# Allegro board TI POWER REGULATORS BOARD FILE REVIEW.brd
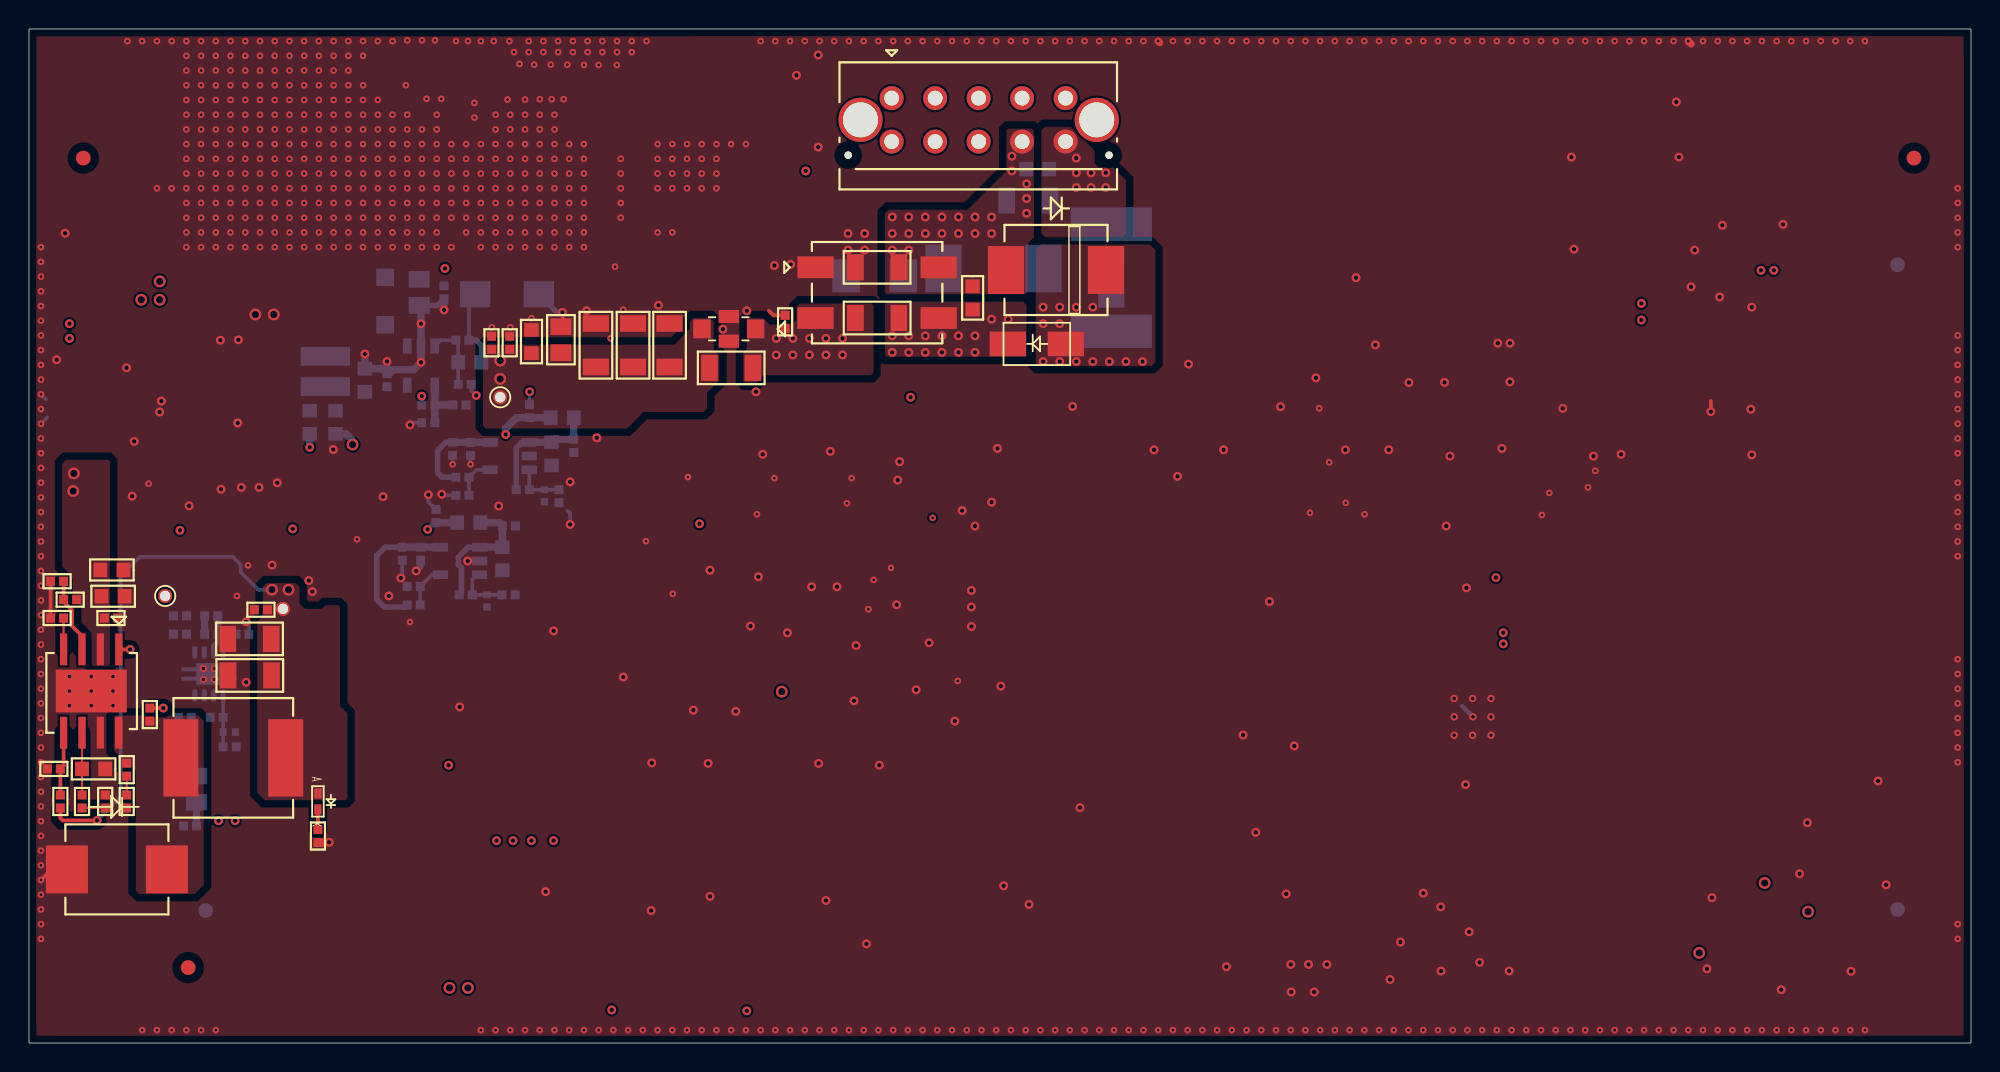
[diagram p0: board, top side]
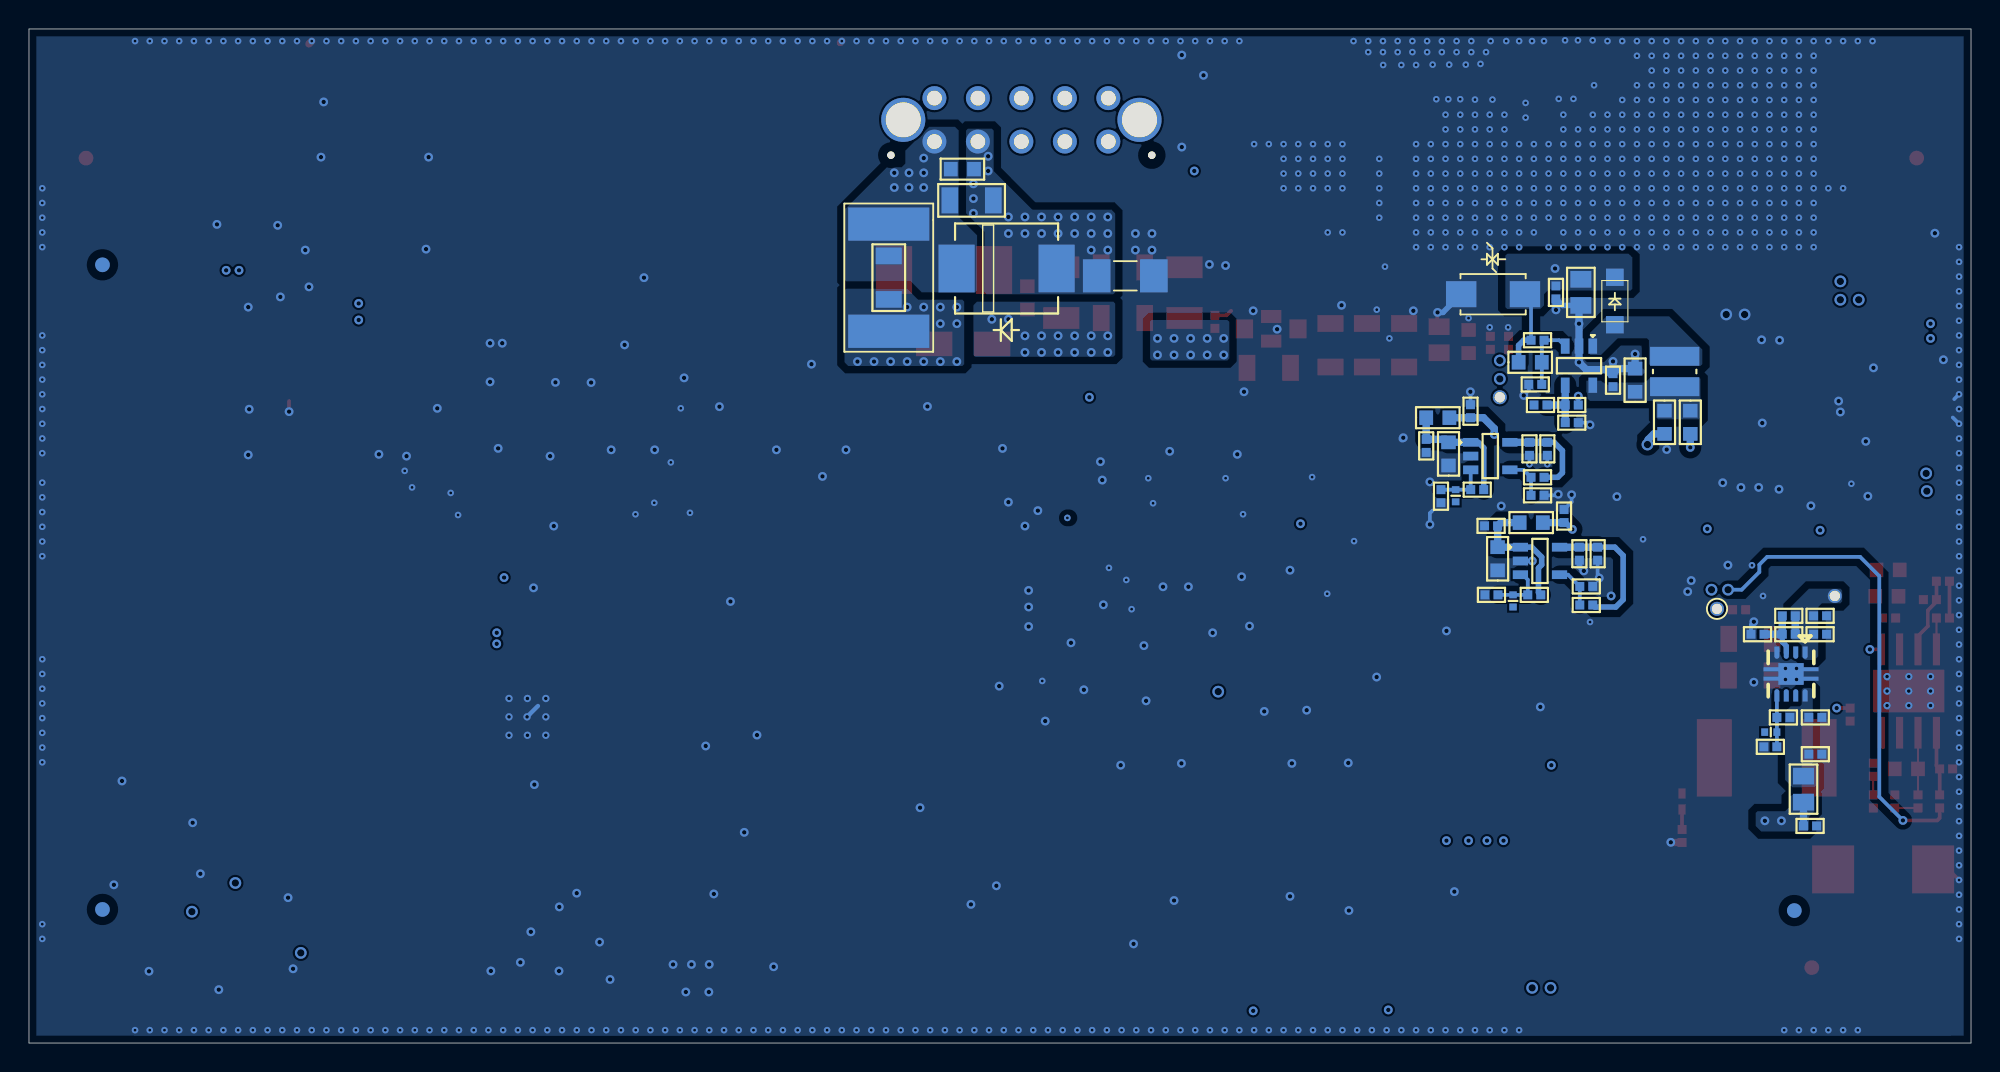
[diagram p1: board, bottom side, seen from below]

Outline 134 x 70 mm; copper layers: TOP, GND, SIG1, SIG2, VCC, BOTTOM. Coordinates in mm from the lower left corner of the outline.
Outline path: 0,70 0,0 134,0 134,70 0,70

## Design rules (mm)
net group DP10: nets CAN1_H CAN1_L
net group DP11: nets CAN2_H CAN2_L
net group POWER: nets LDO1_EN LDO1_FB

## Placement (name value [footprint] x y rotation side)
C106  0.1uF  [0402]  10.41 29.49 180 bottom
C111  2.2uF  [0402]  10.41 28.22 180 bottom
C120  0.1uF  [0402]  12.57 28.22 0 bottom
C484  4.7uF  [0603]  23.18 45.76 90 bottom
C485  100pF  [0603]  30.42 46.99 180 bottom
C486  4.7uF  [0805]  26.92 51.82 270 bottom
C517  0.1uF  [0603]  69.6 60.33 0 bottom
C519  1000pF_3KV  [1808]  60.33 52.96 180 bottom
C523  1uF  [0603]  34.67 48.42 270 top
C524  0.1uF  [0402]  31.91 48.34 270 top
C525  10uF  [0805]  36.7 48.55 270 top
C527  47uF  [1206]  41.68 48.17 270 top
C528  47uF  [1206]  39.12 48.17 270 top
C533  47uF  [1206]  68.96 58.17 0 bottom
C534  0.1uF  [0603]  65.11 51.44 270 top
C540  0.1uF  [0402]  33.17 48.34 270 top
C541  0.1uF  [0402]  52.17 49.78 270 top
C542  47uF  [1206]  44.2 48.17 270 top
C588  4.7uF  [0603]  5.72 32.65 180 top
C590  10000pF  [0402]  5.65 29.34 180 top
C592  22pF  [0603]  4.46 18.92 180 top
C593  10000pF  [0402]  1.94 29.34 0 top
C594  0.1uF  [0402]  8.34 22.67 90 top
C595  47uF  [1206]  15.23 25.38 0 top
C596  47uF  [1206]  15.22 27.9 0 top
C613  4.7uF  [0603]  5.8 30.84 180 top
C614  2200pF  [0402]  3.66 16.68 90 top
C615  0.1uF  [0402]  11.11 14.99 180 bottom
C616  0.1uF  [0402]  10.74 19.94 180 bottom
C620  4.7uF  [0402]  10.74 22.48 180 bottom
C643  0.1uF  [0402]  24.7 45.76 90 bottom
C644  0.1uF  [0402]  28.64 51.82 270 bottom
C648  0.1uF  [0402]  16 29.91 0 top
C670  0.1uF  [0402]  25.76 33.78 270 bottom
C672  0.1uF  [0402]  28.08 36.38 90 bottom
C673  1uF  [0402]  27.02 33.78 270 bottom
C674  0.1uF  [0402]  29.23 41.02 270 bottom
C676  0.1uF  [0402]  34.54 43.61 90 bottom
C677  1uF  [0402]  30.47 41.02 270 bottom
C731  10uF  [0603]  36.05 40.67 90 bottom
C732  10uF  [0603]  32.66 33.43 90 bottom
C733  0.1uF  [0402]  6.74 16.68 90 top
C750  0.1uF  [0402]  33.11 35.7 0 bottom
C751  0.1uF  [0402]  37.59 41.22 270 bottom
D3  LED  [LED_APHXX]  19.94 17.23 270 top
D4  SK53A-LTP  [DIODE_SMA]  71.54 48.26 180 top
D50  MBR0530T1G  [SOD_123]  24.58 49.58 90 bottom
D59  5.0SMDJ18A  [DIODE_DO-214AB]  63.1 53.47 0 bottom
D83  CDBC540-G  [DIODE_SMC-DO-214AB]  2.62 11.99 0 top
D84  5.0SMDJ18A  [DIODE_DO-214AB]  67.41 53.36 0 top
D87  SMAJ18CA  [DIODE_DO-214AC-SMA]  35.18 51.69 180 bottom
E1  ACM9070-701-2PL-TL01  [CMC_ACM9070]  54.27 53.55 0 top
F6  0ZCF0330FF2C  [FUSE_0ZCF0100AF2A]  74.68 56.53 270 bottom
FB33  BLM21SN300SH1D  [0805]  11.56 17.53 90 bottom
FB47  BLM31KN271SN1L  [1206]  74.68 52.83 270 bottom
FB48  BLM31KN271SN1L  [1206]  58.52 50.05 180 top
FB49  BLM31KN271SN1L  [1206]  48.45 46.61 180 top
FB50  BLM31KN271SN1L  [1206]  58.52 53.55 180 top
FB51  74279228111  [0603]  21.15 42.85 270 bottom
FB52  74279228111  [0603]  19.37 42.85 270 bottom
FB67  74279228111  [0603]  30.35 35.93 180 bottom
FB68  74279228111  [0603]  36.79 43.16 180 bottom
J74  0430451024  [MOLEX_430451024]  59.53 65.23 180 top
L4  10uH  [IND_74438336100]  20.45 45.31 90 bottom
L66  4.7uH  [IND_IHLP3232DZERR47M01]  14.1 19.68 0 top
NOREF  -  []  -28.16 28.95 0 top
NOREF#2  -  []  -23.63 27.09 90 top
NOREF#3  -  []  -28.38 27.09 0 top
NOREF#4  -  []  4 0 90 top
NOREF#5  -  []  -33.76 11.11 0 top
NOREF#6  -  []  10.25 37.12 0 top
NOREF#7  -  []  17.75 37.3 0 top
NOREF#8  -  []  -30.16 5.64 0 top
NOREF#9  -  []  0 70 0 top
NOREF#10  -  []  299.21 -187.96 0 top
NOREF#11  -  []  -124.71 2.62 90 top
NOREF#12  -  []  -123.96 2.55 90 top
NOREF#13  -  []  12.25 37.3 0 top
NOREF#14  -  []  -124.71 3.47 0 top
NOREF#15  -  []  -32.31 7.14 90 top
NOREF#16  -  []  -33.76 2.34 90 top
NOREF#17  -  []  -33.16 4.7 0 top
NOREF#18  -  []  -124.88 3.05 0 top
NOREF#19  -  []  10.6 41.2 0 top
NOREF#20  -  []  -30.16 5.64 0 top
NOREF#21  -  []  -30.16 5.64 90 top
NOREF#22  -  []  23.75 37.3 90 top
NOREF#23  -  []  -124.96 3.55 0 top
NOREF#24  -  []  -14.61 3.74 90 top
NOREF#25  -  []  -32.31 7.14 0 top
R19  499E  [0402]  19.94 14.29 270 top
R102  68K, 1%  [0402]  14.73 28.22 0 bottom
R103  33.2K, 1%  [0402]  12.57 29.49 180 bottom
R606  0E  [0402]  29.71 44.04 180 bottom
R607  182K  [0402]  29.91 48.51 0 bottom
R608  13.3K  [0402]  30.07 45.47 180 bottom
R609  51K  [0402]  27.55 44.04 180 bottom
R610  10K  [0402]  27.55 42.82 0 bottom
R706  620K  [0402]  2.84 30.61 0 top
R707  130K  [0402]  1.94 31.88 0 top
R709  10.2k  [0402]  2.17 16.68 270 top
R710  1.96K  [0402]  1.72 18.92 0 top
R711  10K  [0402]  12.95 22.48 180 bottom
R720  37.4K  [0402]  5.26 16.68 270 top
R771  10K  [0402]  33.09 30.94 0 bottom
R772  10K  [0402]  30.13 30.94 0 bottom
R773  10K  [0402]  36.57 37.75 270 bottom
R774  10K  [0402]  34.07 38.2 0 bottom
R839  5.1E  [0402]  6.74 18.87 90 top
R895  0E  [0402C]  31.6 30.52 270 bottom
R896  0E  [0402C]  35.56 37.78 270 bottom
R904  100k  [0402]  26.55 31.52 180 bottom
R905  50k  [0402]  26.55 30.24 0 bottom
R907  187k  [0402]  29.91 39.05 0 bottom
R908  75k  [0402]  29.91 37.81 0 bottom
R921  0E  [0402C]  13.82 21.46 180 bottom
R922  10K  [0402]  13.85 20.45 0 bottom
TP76  TP  [TPXTHX50MIL]  9.4 30.86 0 top
TP79  TP  [TPXTHX50MIL]  32.51 44.58 0 top
TP102  TP  [TPXTHX50MIL]  17.53 29.97 270 bottom
U13  TPS73701DRBR  [PVSONX0_65X3_15X3_15X1_00-9]  11.45 26.95 0 bottom
U25  LM2733XMF/NOPB  [SOT23X0_95X3_05X1_75X1_45-5]  26.1 48.11 0 bottom
U69  YFF31HC2A103MT000N  [EMIFIL_YFF31HC]  50.14 49.3 180 top
U74  TPS54531DDAR  [HSOICX1_27X5_00X4_00X1_70-9]  6.2 27.17 180 top
U77  RT9053AGB  [SOT23X0_95X3_05X1_75X1_10-5]  31.09 34.23 270 bottom
U78  RT9053AGB  [SOT23X0_95X3_05X1_75X1_10-5]  34.52 41.47 270 bottom
UNK*  -  [unnamed#2]  10.99 5.21 0 top
UNK*#2  -  [unnamed#2]  130.07 61.09 0 top
UNK*#3  -  [unnamed#2]  3.75 61.09 0 top
UNK*#4  -  [unnamed#2]  128.93 9.22 180 bottom
UNK*#5  -  [unnamed#2]  128.93 53.72 180 bottom
UNK*#6  -  [unnamed#2]  12.19 9.14 180 bottom

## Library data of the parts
C106 C120 C519 C615 C616 C670 C672 C674 C676 C750 C751 = CAP NP
C111 C484-C486 C620 C643 C644 C673 C677 C731 C732 = CAPACITOR NON-POL
C517 C523-C525 C527 C528 C533 C534 C540-C542 C588 C590 C592-C596 C613 C614 C648 C733 = C
D3 = LED
D4 D59 D84 D87 = DIODE_SCHTKY_4
D50 D83 = DIODE SCHOTTKY
E1 = INDUCTOR IRON_0
F6 = FUSE THERMAL
FB33 FB47-FB52 FB67 FB68 = INDUCTOR FERRITE
J74 = 0430451024_1
L4 L66 = INDUCTOR
R19 R102 R103 R606-R610 R895 R896 R904 R905 R907 R921 = RES
R706 R707 R709-R711 R720 R771-R774 R922 = R_1
R839 R908 = R
TP76 TP79 TP102 = T POINT R
U13 = TPS73701DCQ_1
U25 = LM2733XMF/NOPB
U69 = E_2
U74 = TPS54531DDAR
U77 U78 = TLV70012QDDCRQ1_0

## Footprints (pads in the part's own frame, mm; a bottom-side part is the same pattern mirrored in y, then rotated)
0402
  rect 0.62x0.62 smd: 1(-0.45,0) 2(0.45,0)
0402C
  rect 0.48x0.521 smd: 1(-0.419,0) 2(0.419,0)
0603
  rect 0.95x1 smd: 1(-0.8,0) 2(0.8,0)
0805
  rect 1.15x1.45 smd: 1(-0.9,0) 2(0.9,0)
1206
  rect 1.15x1.8 smd: 1(-1.5,0) 2(1.5,0)
1808
  rect 1.91x2.29 smd: 1(0,0) 2(3.942,0)
CMC_ACM9070
  rect 2.5x1.5 smd: 1(0,0) 2(0,-3.5) 3(8.5,-3.5) 4(8.5,0)
DIODE_DO-214AB
  rect 2.5x3.3 smd: 1(0,0) 2(6.9,0)
DIODE_DO-214AC-SMA
  rect 2.1x1.8 smd: 1(0,0) 2(4.4,0)
DIODE_SMA
  rect 2.5x1.7 smd: 1(0,0) 2(4,0)
DIODE_SMC-DO-214AB
  rect 2.9x3.3 smd: 1(0,0) 2(6.9,0)
EMIFIL_YFF31HC
  rect 1.199x1.301 smd: 1(0,0) 3(3.701,0)
  rect 1.399x0.899 smd: 2(1.849,-0.851) 4(1.849,0.851)
FUSE_0ZCF0100AF2A
  rect 2.301x5.601 smd: 1(0,0) 2(7.399,0)
HSOICX1_27X5_00X4_00X1_70-9
  rect 0.5x2.2 smd: 1(0,0) 2(1.27,0) 3(2.54,0) 4(3.81,0) 5(3.81,5.751) 6(2.54,5.751) 7(1.27,5.751) 8(0,5.751)
  rect 4.9x2.949 smd: 9(1.905,2.875)
IND_74438336100
  rect 1.3x3.4 smd: 1(0,0) 2(2.1,0)
IND_IHLP3232DZERR47M01
  rect 2.413x5.334 smd: 1(-3.619,0) 2(3.619,0)
LED_APHXX
  rect 0.701x0.5 smd: 1(0,0) 2(1.1,0)
MOLEX_430451024
  round 0.51 hole 1.02 unplated: (-15,3.94) (3,3.94)
  round 3.045 hole 2.41: (-14.15,1.5) (2.15,1.5)
  round 1.655 hole 1.02: 1(0,0) 2(-3,0) 3(-6,0) 4(-9,0) 5(-12,0) 6(0,3) 7(-3,3) 8(-6,3) 9(-9,3) 10(-12,3)
PVSONX0_65X3_15X3_15X1_00-9
  custom 0.088x0.088 smd: 1(0,0) 2(0.65,0) 3(1.3,0) 4(1.95,0) 5(1.95,2.95) 6(1.3,2.95) 7(0.65,2.95) 8(0,2.95)
  custom 0.375x0.375 smd: 9(0.975,1.475)
SOD_123
  rect 1.2x1.22 smd: 1(0,0) 2(3.28,0)
SOT23X0_95X3_05X1_75X1_10-5
  rect 0.6x1.05 smd: 1(0,0) 2(0.95,0) 3(1.9,0) 4(1.9,2.7) 5(0,2.7)
SOT23X0_95X3_05X1_75X1_45-5
  rect 0.6x1.05 smd: 1(0,0) 2(0.95,0) 3(1.9,0) 4(1.9,2.7) 5(0,2.7)
TPXTHX50MIL
  round 0.965 hole 0.711: 1(0,0)
unnamed#2
  round 1.016 smd: (0,0)

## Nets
18V_OUT_EN_GPIO1_IO10: R606.1
18V_SHDN: R606.2 R609.1 R610.2 U25.4(S\H\D\N\)
GND: C106.2 C111.2 C484.2 C486.2 C519.2 C523.1 C524.1 C525.1 C527.1 C528.1 C540.1 C541.1 C542.1 C588.1 C590.1 C592.1 C593.1 C595.1 C596.1 C613.1 C615.2 C616.2 C620.2 C643.2 C644.2 C648.1 C670.2 C672.2 C673.2 C674.2 C676.2 C677.2 C731.1 C732.1 C733.1 C750.2 C751.2 D83.1(ANODE) D87.1(A) E1.1 FB50.2 R19.2 R102.2 R608.1 R610.1 R707.1 R710.1 R720.1 R771.2 R773.2 R904.2 R908.1 R922.2 U13.4(GND1) U13.9(PGND) U25.2(GND) U69.2 U69.4 U74.7(GND) U74.9(TP) U77.2(GND) U78.2(GND)
VBAT_12V: C523.2 C524.2 C525.2 C527.2 C528.2 C540.2 C542.2 C588.2 C590.2 C613.2 FB49.2 R706.2 TP79.1(TP) U69.3 U74.2(VIN)
VBAT_12V_EN: R706.1 R707.2 U74.3(EN)
VCC_1V2: C670.1 C673.1 R905.1 U77.5(OUT)
VCC_1V8: C106.1 C111.1 C120.1 R103.2 TP76.1(TP) U13.1(OUT)
VCC_2V8: C674.1 C677.1 R907.1 U78.5(OUT)
VCC_3V3: C615.1 C672.1 C676.1 FB33.1 FB51.2 FB67.2 FB68.2 R609.2
VCC_3V3_LDO: C616.1 C620.1 FB33.2 R711.2 U13.8(IN)
VCC_3V3_LDO2: C732.2 C750.1 FB67.1 R772.1 U77.1(VIN)
VCC_3V3_LDO3: C731.2 C751.1 FB68.1 R774.1 U78.1(VIN)
VCC_5V: C595.2 C596.2 C648.2 D3.1(ANODE) FB52.2 L66.2 R709.2 TP102.1(TP)
VCC_FIL: C484.1 C643.1 FB51.1 FB52.1 L4.1 U25.5(VIN)
VIN_12V: C517.2 C533.2 D59.2(C) F6.1 FB47.1 J74.10(VIN_12)
ANALOG IN_2: J74.5(ANALOG IN_2)
ANALOG_OUT: J74.3(ANALOG OUT)
CAN1_H: J74.7(CAN1_H)
CAN1_L: J74.6(CAN1_L)
CAN2_H: J74.1(CAN2_H)
CAN2_L: J74.2(CAN2_L)
CONN_GND: C517.1 C519.1 C533.1 C534.1 D59.1(A) D84.1(A) E1.4 FB50.1 J74.9(CONN_GND)
LDO1_EN: R711.1 R921.2 R922.1 U13.5(EN)
LDO1_EN_GPIO5_IO00: R921.1
LDO1_FB: C120.2 R102.1 R103.1 U13.3(FB/NR)
LDO2_EN: R771.1 R772.2 R895.1 U77.3(EN)
LDO2_EN_GPIO4_IO10: R895.2
LDO3_EN: R773.1 R774.2 R896.1 U78.3(EN)
LDO3_EN_GPIO4_IO31: R896.2
VOUT_12V: J74.4(VP-P_IN)
VOUT_18V: C485.1 C486.1 C644.1 D50.2(CATHODE) D87.2(C) J74.8(VOUT_18V) R607.2
N16733345: C534.2 D4.2(C) E1.3 FB48.1
N16733349: C541.2 E1.2 FB48.2 FB49.1 U69.1
N16733417: C594.1 D83.2(CATHODE) L66.1 R839.2 U74.8(PH)
N16733425: C733.2 R839.1
N16733771: C592.2 C614.2 U74.6(COMP)
N16733783: C614.1 R720.2
N16733885: C593.2 U74.4(SS)
N16733923: C594.2 U74.1(BOOT)
N16734049: D4.1(A) D84.2(C) F6.2 FB47.2
N16734163: R709.1 R710.2 U74.5(VSENSE)
N16734965: D3.2(CATHODE) R19.1
N16737795: R904.1 R905.2 U77.4(FB)
N16737935: R907.2 R908.2 U78.4(FB)
N16741203: D50.1(ANODE) L4.2 U25.1(SW)
N16741257: C485.2 R607.1 R608.2 U25.3(FB)

Pads without a net: U13 2 6 7

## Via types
v1: diameter 0.61, hole 0.305, TOP to BOTTOM, 257 vias
v2: diameter 0.813, hole 0.508, TOP to BOTTOM, 18 vias
v3: diameter 0.457, hole 0.203, TOP to BOTTOM, 701 vias
v4: diameter 0.508, hole 0.254, TOP to BOTTOM, 22 vias

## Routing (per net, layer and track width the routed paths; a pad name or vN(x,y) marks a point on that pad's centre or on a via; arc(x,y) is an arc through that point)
18V_SHDN: length 3.8
  BOTTOM w0.508: R606.2 R609.1 ; R609.1 U25.4 ; R609.1 R610.2
GND: length 38.5
  TOP w0.254: 78.01,69.07 78.11,68.97 ; C528.1 38.85,49.67 38.48,50.04 v1(38.48,50.55) ; v3(0.83,11.25) 1.56,11.99 D83.1 ; v1(36.81,50.43) 36.83,50.41 36.83,49.45 ; R707.1 C593.1 ; 51.05,50.55 51.37,50.23 C541.1 ; 116.05,44.32 v1(116.05,43.59)
  TOP w0.508: R19.2 20.7,13.84 v1(20.71,13.86) ; v3(77.92,69.16) 78.01,69.07 ; v3(114.49,69.16) 114.68,68.97
  BOTTOM w0.254: v1(34.54,44.96) 34.54,44.95 C676.2 ; 1.26,43.18 v3(0.83,42.75) ; v1(25.65,32.1) 25.65,32.26 25.76,32.37 C670.2 ; C674.2 v3(29.23,39.95) ; 37.17,36.75 37.34,36.58 v1(37.34,35.8) ; U77.2 v1(30.27,33.28) ; R102.2 15.18,28.89 v1(14.99,29.08) ; v3(90.11,0.89) 90.1,0.89 ; v1(30.86,44.7) 30.52,45.05 R608.1 ; 1.16,44.45 v3(0.83,44.78) ; R610.1 26.44,42.82 v1(26.29,42.67) ; v1(27.56,37.85) 27.56,37.35 C672.2 ; v1(28.48,37.88) 28.55,37.81 R908.1 ; C677.2 v3(30.47,39.95)
  BOTTOM w0.3: v4(99.63,22.52) 98.88,23.27
  BOTTOM w0.381: C673.2 27.02,32.9 v1(26.72,32.59) ; C644.2 28.19,50.92 C486.2 ; D87.1 36.43,50.43 v1(36.81,50.43)
  BOTTOM w0.508: v1(23.18,47.56) C484.2 24.35,46.56 C643.2 ; C643.2 v1(24.7,47.05) ; C643.2 24.87,46.21 25.15,46.48 26.54,46.48 v1(27.05,46.99) U25.2 v1(27.05,49.66) 27.05,50.79 C486.2 ; C644.2 v1(28.64,50.61) ; 39.25,41.71 v1(39.17,41.78)
  vias: v1(1.91,47.17) v1(2.49,55.9) v1(6.73,46.61) v1(7.12,37.75) v1(7.26,41.53) v1(9.02,43.56) v1(9.13,44.31) v1(11.05,37.08) v1(13.21,48.51) v1(13.25,38.23) v1(14.45,48.54) v1(14.4,42.8) v1(14.65,38.35) v1(14.99,24.91) v1(15.88,38.35) v1(16.77,32.99) v1(17.13,38.68) v1(19.31,31.92) v1(19.55,31.16) v1(21,40.97) v1(24.43,37.72) v1(24.83,30.86) v1(29.72,23.2) v1(32.41,37.07) v1(35.65,10.45) v1(36.2,28.45) v1(37.34,38.73) v1(41.01,25.26) v1(42.93,9.14) v1(42.97,19.34) v1(43.43,50.93) v1(45.84,22.98) v1(46.86,19.3) v1(46.99,32.64) v1(46.99,10.13) v1(47.88,49.28) v1(48.77,22.89) v1(49.53,50.55) v1(49.78,28.78) v1(50.16,44.96) v1(50.33,32.19) v1(50.63,40.64) v1(51.44,53.67) v1(52.33,28.32) v1(52.55,53.75) v1(52.96,66.8) v1(54,31.5) v1(54.46,68.2) v1(54.46,61.85) v1(54.48,19.3) v1(54.99,9.84) v1(55.29,40.85) v1(55.75,31.5) v1(56.52,55.88) v1(56.52,54.74) v1(56.92,23.62) v1(57.07,27.43) v1(57.66,55.88) v1(57.66,54.74) v1(57.78,6.84) v1(58.67,19.18) v1(59.94,38.86) v1(59.87,30.25) v1(60.07,40.13) v1(61.21,24.38) v1(62.1,27.63) v1(63.88,22.23) v1(64.39,36.75) v1(65.03,31.24) v1(65.02,30.1) v1(65.02,28.75) v1(65.28,35.69) v1(66.42,37.34) v1(66.83,41.05) v1(67.06,24.64) v1(67.25,10.85) v1(69.01,9.57) v1(72.01,43.94) v1(72.52,16.25) v1(77.63,40.95) v1(79.25,39.12) v1(80.01,46.86) v1(82.43,40.95) v1(82.62,5.26) v1(83.77,21.26) v1(84.65,14.54) v1(85.6,30.48) v1(86.36,43.93) v1(86.75,10.29) v1(87.06,5.42) v1(87.09,3.52) v1(87.31,20.5) v1(88.29,5.42) v1(88.68,3.52) v1(88.8,45.92) v1(89.56,5.42) v1(90.83,40.95) v1(91.57,52.83) v1(92.9,48.19) v1(93.83,40.95) v1(93.91,4.39) v1(94.63,6.97) v1(95.21,45.59) v1(96.21,10.34) v1(97.41,9.4) v1(97.43,4.97) v1(97.67,45.6) v1(97.79,35.69) v1(98.04,40.51) v1(99.13,17.84) v1(99.19,31.42) v1(99.37,7.68) v1(100.09,5.57) v1(101.35,48.31) v1(101.63,41.05) v1(102.13,4.97) v1(102.19,48.31) v1(102.19,45.64) v1(105.83,43.81) v1(106.43,61.15) v1(106.6,54.8) v1(107.95,40.51) v1(109.86,40.64) v1(113.67,64.96) v1(113.85,61.15) v1(114.68,52.2) v1(114.94,54.74) v1(115.78,5.13) v1(116.12,10.03) v1(116.66,51.5) v1(116.84,56.45) v1(118.81,43.75) v1(118.87,50.8) v1(118.87,40.6) v1(120.9,3.68) v1(121.03,56.51) v1(122.17,11.68) v1(122.71,15.21) v1(125.72,4.95) v1(127.58,18.09) v1(128.14,10.92) v2(15.62,50.29) v2(16.89,50.29) v3(0.83,54.94) v3(0.83,53.92) v3(0.83,52.91) v3(0.83,51.89) v3(0.83,50.88) v3(0.83,49.86) v3(0.83,48.84) v3(0.83,47.83) v3(0.83,46.81) v3(0.83,45.8) v3(0.83,43.76) v3(0.83,41.73) v3(0.83,40.72) v3(0.83,39.7) v3(0.83,38.68) v3(0.83,37.67) v3(0.83,36.65) v3(0.83,35.64) v3(0.83,34.62) v3(0.83,33.6) v3(0.83,32.59) v3(0.83,31.57) v3(0.83,30.56) v3(0.83,29.54) v3(0.83,28.52) v3(0.83,27.51) v3(0.83,26.49) v3(0.83,25.48) v3(0.83,24.46) v3(0.83,23.44) v3(0.83,22.43) v3(0.83,21.41) v3(0.83,20.4) v3(0.83,19.38) v3(0.83,18.36) v3(0.83,17.35) v3(0.83,16.33) v3(0.83,15.32) v3(0.83,14.3) v3(0.83,13.28) v3(0.83,12.27) v3(0.83,10.24) v3(0.83,9.22) v3(0.83,8.2) v3(0.83,7.19) v3(6.8,69.16) v3(7.81,69.16) v3(7.81,0.89) v3(8.26,38.61) v3(8.83,69.16) v3(8.83,59) v3(8.83,0.89) v3(9.84,69.16) v3(9.84,59) v3(9.84,0.89) v3(10.86,69.16) v3(10.86,68.15) v3(10.86,67.13) v3(10.86,66.12) v3(10.86,65.1) v3(10.86,64.08) v3(10.86,63.07) v3(10.86,62.05) v3(10.86,61.04) v3(10.86,60.02) v3(10.86,59) v3(10.86,57.99) v3(10.86,56.97) v3(10.86,55.96) v3(10.86,54.94) v3(10.86,0.89) v3(11.88,69.16) v3(11.88,68.15) v3(11.88,67.13) v3(11.88,66.12) v3(11.88,65.1) v3(11.88,64.08) v3(11.88,63.07) v3(11.88,62.05) v3(11.88,61.04) v3(11.88,60.02) v3(11.88,59) v3(11.88,57.99) v3(11.88,56.97) v3(11.88,55.96) v3(11.88,54.94) v3(11.88,0.89) v3(12.89,69.16) v3(12.89,68.15) v3(12.89,67.13) v3(12.89,66.12) v3(12.89,65.1) v3(12.89,64.08) v3(12.89,63.07) v3(12.89,62.05) v3(12.89,61.04) v3(12.89,60.02) v3(12.89,59) v3(12.89,57.99) v3(12.89,56.97) v3(12.89,55.96) v3(12.89,54.94) v3(12.89,0.89) v3(13.91,69.16) v3(13.91,68.15) v3(13.91,67.13) v3(13.91,66.12) v3(13.91,65.1) v3(13.91,64.08) v3(13.91,63.07) v3(13.91,62.05) v3(13.91,61.04) v3(13.91,60.02) v3(13.91,59) v3(13.91,57.99) v3(13.91,56.97) v3(13.91,55.96) v3(13.91,54.94) v3(14.35,30.86) v3(14.92,69.16) v3(14.92,68.15) v3(14.92,67.13) v3(14.92,66.12) v3(14.92,65.1) v3(14.92,64.08) v3(14.92,63.07) v3(14.92,62.05) v3(14.92,61.04) v3(14.92,60.02) v3(14.92,59) v3(14.92,57.99) v3(14.92,56.97) v3(14.92,55.96) v3(14.92,54.94) v3(15.11,32.98) v3(15.94,69.16) v3(15.94,68.15) v3(15.94,67.13) v3(15.94,66.12) v3(15.94,65.1) v3(15.94,64.08) v3(15.94,63.07) v3(15.94,62.05) v3(15.94,61.04) v3(15.94,60.02) v3(15.94,59) v3(15.94,57.99) v3(15.94,56.97) v3(15.94,55.96) v3(15.94,54.94) v3(16.96,69.16) v3(16.96,68.15) v3(16.96,67.13) v3(16.96,66.12) v3(16.96,65.1) v3(16.96,64.08) v3(16.96,63.07) v3(16.96,62.05) v3(16.96,61.04) v3(16.96,60.02) v3(16.96,59) v3(16.96,57.99) v3(16.96,56.97) v3(16.96,55.96) v3(16.96,54.94) v3(17.97,69.16) v3(17.97,68.15) v3(17.97,67.13) v3(17.97,66.12) v3(17.97,65.1) v3(17.97,64.08) v3(17.97,63.07) v3(17.97,62.05) v3(17.97,61.04) v3(17.97,60.02) v3(17.97,59) v3(17.97,57.99) v3(17.97,56.97) v3(17.97,55.96) v3(17.97,54.94) v3(18.99,69.16) v3(18.99,68.15) v3(18.99,67.13) v3(18.99,66.12) v3(18.99,65.1) v3(18.99,64.08) v3(18.99,63.07) v3(18.99,62.05) v3(18.99,61.04) v3(18.99,60.02) v3(18.99,59) v3(18.99,57.99) v3(18.99,56.97) v3(18.99,55.96) v3(18.99,54.94) v3(20,69.16) v3(20,68.15) v3(20,67.13) v3(20,66.12) v3(20,65.1) v3(20,64.08) v3(20,63.07) v3(20,62.05) v3(20,61.04) v3(20,60.02) v3(20,59) v3(20,57.99) v3(20,56.97) v3(20,55.96) v3(20,54.94) v3(21.02,69.16) v3(21.02,68.15) v3(21.02,67.13) v3(21.02,66.12) v3(21.02,65.1) v3(21.02,64.08) v3(21.02,63.07) v3(21.02,62.05) v3(21.02,61.04) v3(21.02,60.02) v3(21.02,59) v3(21.02,57.99) v3(21.02,56.97) v3(21.02,55.96) v3(21.02,54.94) v3(22.04,69.16) v3(22.04,68.15) v3(22.04,67.13) v3(22.04,66.12) v3(22.04,65.1) v3(22.04,64.08) v3(22.04,63.07) v3(22.04,62.05) v3(22.04,61.04) v3(22.04,60.02) v3(22.04,59) v3(22.04,57.99) v3(22.04,56.97) v3(22.04,55.96) v3(22.04,54.94) v3(22.63,34.77) v3(23.05,69.16) v3(23.05,68.15) v3(23.05,66.12) v3(23.05,65.1) v3(23.05,64.08) v3(23.05,63.07) v3(23.05,62.05) v3(23.05,61.04) v3(23.05,60.02) v3(23.05,59) v3(23.05,57.99) v3(23.05,56.97) v3(23.05,55.96) v3(23.05,54.94) v3(24.07,69.16) v3(24.07,65.1) v3(24.07,64.08) v3(24.07,63.07) v3(24.07,62.05) v3(24.07,61.04) v3(24.07,60.02) v3(24.07,59) v3(24.07,57.99) v3(24.07,56.97) v3(24.07,55.96) v3(24.07,54.94) v3(25.08,69.16) v3(25.08,64.08) v3(25.08,63.07) v3(25.08,62.05) v3(25.08,61.04) v3(25.08,60.02) v3(25.08,59) v3(25.08,57.99) v3(25.08,56.97) v3(25.08,55.96) v3(25.08,54.94) v3(26.01,66.12) v3(26.11,69.22) v3(26.1,64.08) v3(26.1,63.07) v3(26.1,62.05) v3(26.1,61.04) v3(26.1,60.02) v3(26.1,59) v3(26.1,57.99) v3(26.1,56.97) v3(26.1,55.96) v3(26.1,54.94) v3(26.29,29.06) v3(27.12,69.22) v3(27.12,63.07) v3(27.12,62.05) v3(27.12,61.04) v3(27.12,60.02) v3(27.12,59) v3(27.12,57.99) v3(27.12,56.97) v3(27.12,55.96) v3(27.12,54.94) v3(27.43,65.18) v3(28.01,69.22) v3(28.13,64.08) v3(28.13,63.07) v3(28.13,62.05) v3(28.13,61.04) v3(28.13,60.02) v3(28.13,59) v3(28.13,57.99) v3(28.13,56.97) v3(28.13,55.96) v3(28.13,54.94) v3(28.45,65.18) v3(29.15,62.05) v3(29.15,61.04) v3(29.15,60.02) v3(29.15,59) v3(29.15,57.99) v3(29.15,56.97) v3(29.15,54.94) v3(29.46,69.16) v3(30.16,62.05) v3(30.16,61.04) v3(30.16,60.02) v3(30.16,59) v3(30.16,57.99) v3(30.16,56.97) v3(30.16,55.96) v3(30.29,69.16) v3(30.73,64.9) v3(30.73,63.88) v3(31.18,69.16) v3(31.18,62.05) v3(31.18,61.04) v3(31.18,60.02) v3(31.18,59) v3(31.18,57.99) v3(31.18,56.97) v3(31.18,55.96) v3(31.18,54.94) v3(31.18,0.89) v3(31.94,49.4) v3(32.07,69.16) v3(32.2,64.08) v3(32.2,63.07) v3(32.2,62.05) v3(32.2,61.04) v3(32.2,60.02) v3(32.2,59) v3(32.2,57.99) v3(32.2,56.97) v3(32.2,55.96) v3(32.2,54.94) v3(32.2,0.89) v3(33.02,65.13) v3(33.15,69.16) v3(33.21,64.08) v3(33.21,63.07) v3(33.21,62.05) v3(33.21,61.04) v3(33.21,60.02) v3(33.21,59) v3(33.21,57.99) v3(33.21,56.97) v3(33.21,55.96) v3(33.21,54.94) v3(33.21,49.4) v3(33.21,0.89) v3(33.47,68.4) v3(33.85,67.59) v3(34.23,65.13) v3(34.23,64.08) v3(34.23,63.07) v3(34.23,62.05) v3(34.23,61.04) v3(34.23,60.02) v3(34.23,59) v3(34.23,57.99) v3(34.23,56.97) v3(34.23,55.96) v3(34.23,54.94) v3(34.23,0.89) v3(34.48,69.16) v3(34.48,68.4) v3(34.67,50.04) v3(34.86,67.54) v3(35.24,65.15) v3(35.24,64.08) v3(35.24,63.07) v3(35.24,62.05) v3(35.24,61.04) v3(35.24,60.02) v3(35.24,59) v3(35.24,57.99) v3(35.24,56.97) v3(35.24,55.96) v3(35.24,54.94) v3(35.24,0.89) v3(35.5,69.16) v3(35.5,68.4) v3(36.01,67.54) v3(36.07,65.15) v3(36.26,64.08) v3(36.26,63.07) v3(36.26,62.05) v3(36.26,61.04) v3(36.26,60.02) v3(36.26,59) v3(36.26,57.99) v3(36.26,56.97) v3(36.26,55.96) v3(36.26,54.94) v3(36.26,0.89) v3(36.51,69.16) v3(36.51,68.4) v3(36.89,65.15) v3(37.15,67.54) v3(37.28,62.05) v3(37.28,61.04) v3(37.28,60.02) v3(37.28,59) v3(37.28,57.99) v3(37.28,56.97) v3(37.28,55.96) v3(37.28,54.94) v3(37.28,0.89) v3(37.53,69.16) v3(37.53,68.4) v3(38.29,67.51) v3(38.29,62.05) v3(38.29,61.04) v3(38.29,60.02) v3(38.29,59) v3(38.29,57.99) v3(38.29,56.97) v3(38.29,55.96) v3(38.29,54.94) v3(38.29,0.89) v3(38.55,69.16) v3(38.55,68.4) v3(39.31,67.51) v3(39.31,0.89) v3(39.56,69.16) v3(39.56,68.4) v3(40.13,48.64) v3(40.32,0.89) v3(40.44,53.59) v3(40.58,69.16) v3(40.58,68.4) v3(40.56,67.51) v3(40.83,61.04) v3(40.83,60.02) v3(40.83,59) v3(40.83,57.99) v3(40.83,56.97) v3(41,50.62) v3(41.34,0.89) v3(41.59,69.16) v3(41.59,68.4) v3(42.36,0.89) v3(42.61,69.16) v3(42.57,34.65) v3(43.37,62.05) v3(43.37,61.04) v3(43.37,60.02) v3(43.37,59) v3(43.37,55.96) v3(43.37,0.89) v3(44.39,62.05) v3(44.39,61.04) v3(44.39,60.02) v3(44.39,59) v3(44.39,55.96) v3(44.42,31.01) v3(44.39,0.89) v3(45.4,62.05) v3(45.4,61.04) v3(45.4,60.02) v3(45.4,59) v3(45.4,0.89) v3(45.47,39.07) v3(46.42,62.05) v3(46.42,61.04) v3(46.42,60.02) v3(46.42,59) v3(46.42,0.89) v3(47.44,62.05) v3(47.44,61.04) v3(47.44,60.02) v3(47.44,59) v3(47.44,0.89) v3(48.45,62.05) v3(48.45,0.89) v3(49.47,62.05) v3(49.47,0.89) v3(50.23,36.5) v3(50.48,69.16) v3(50.48,0.89) v3(51.44,38.99) v3(51.5,69.16) v3(51.5,0.89) v3(52.52,69.16) v3(52.52,0.89) v3(53.53,69.16) v3(53.53,0.89) v3(54.55,69.16) v3(54.55,0.89) v3(55.56,69.16) v3(55.56,0.89) v3(56.44,37.26) v3(56.58,69.16) v3(56.58,0.89) v3(56.77,38.99) v3(57.6,69.16) v3(57.6,0.89) v3(57.92,29.95) v3(58.29,31.97) v3(58.61,69.16) v3(58.61,0.89) v3(59.48,32.8) v3(59.63,69.16) v3(59.63,0.89) v3(60.64,69.16) v3(60.64,0.89) v3(61.66,69.16) v3(61.66,0.89) v3(62.68,69.16) v3(62.68,0.89) v3(63.69,69.16) v3(63.69,0.89) v3(64.08,24.99) v3(64.71,69.16) v3(64.71,0.89) v3(65.72,69.16) v3(65.72,0.89) v3(66.74,69.16) v3(66.74,0.89) v3(67.76,69.16) v3(67.76,0.89) v3(68.77,69.16) v3(68.77,0.89) v3(69.79,69.16) v3(69.79,0.89) v3(70.8,69.16) v3(70.8,0.89) v3(71.82,69.16) v3(71.82,0.89) v3(72.84,69.16) v3(72.84,0.89) v3(73.85,69.16) v3(73.85,0.89) v3(74.87,69.16) v3(74.87,0.89) v3(75.88,69.16) v3(75.88,0.89) v3(76.9,69.16) v3(76.9,0.89) v3(77.92,0.89) v3(78.93,69.16) v3(78.93,0.89) v3(79.95,69.16) v3(79.95,0.89) v3(80.96,69.16) v3(80.96,0.89) v3(81.98,69.16) v3(81.98,0.89) v3(83,69.16) v3(83,0.89) v3(84.01,69.16) v3(84.01,0.89) v3(85.03,69.16) v3(85.03,0.89) v3(86.04,69.16) v3(86.04,0.89) v3(87.06,69.16) v3(87.06,0.89) v3(88.08,69.16) v3(88.08,0.89) v3(88.39,36.6) v3(89.03,43.81) v3(89.09,69.16) v3(89.09,0.89) v3(89.71,40.08) v3(90.11,69.16) v3(90.86,37.29) v3(91.12,69.16) v3(91.12,0.89) v3(92.14,69.16) v3(92.14,0.89) v3(92.15,36.5) v3(93.16,69.16) v3(93.16,0.89) v3(94.17,69.16) v3(94.17,0.89) v3(95.19,69.16) v3(95.19,0.89) v3(96.2,69.16) v3(96.2,0.89) v3(97.22,69.16) v3(97.22,0.89) v3(98.24,69.16) v3(98.24,0.89) v3(99.25,69.16) v3(99.25,0.89) v3(100.27,69.16) v3(100.27,0.89) v3(101.28,69.16) v3(101.28,0.89) v3(102.3,69.16) v3(102.3,0.89) v3(103.32,69.16) v3(103.32,0.89) v3(104.33,69.16) v3(104.33,0.89) v3(104.39,36.45) v3(104.9,37.97) v3(105.35,69.16) v3(105.35,0.89) v3(106.36,69.16) v3(106.36,0.89) v3(107.38,69.16) v3(107.38,0.89) v3(107.57,38.35) v3(108.08,39.5) v3(108.4,69.16) v3(108.4,0.89) v3(109.41,69.16) v3(109.41,0.89) v3(110.43,69.16) v3(110.43,0.89) v3(111.44,69.16) v3(111.44,0.89) v3(112.46,69.16) v3(112.46,0.89) v3(113.48,69.16) v3(113.48,0.89) v3(114.49,0.89) v3(115.51,69.16) v3(115.51,0.89) v3(116.52,69.16) v3(116.52,0.89) v3(117.54,69.16) v3(117.54,0.89) v3(118.56,69.16) v3(118.56,0.89) v3(119.57,69.16) v3(119.57,0.89) v3(120.59,69.16) v3(120.59,0.89) v3(121.6,69.16) v3(121.6,0.89) v3(122.62,69.16) v3(122.62,0.89) v3(123.64,69.16) v3(123.64,0.89) v3(124.65,69.16) v3(124.65,0.89) v3(125.67,69.16) v3(125.67,0.89) v3(126.68,69.16) v3(126.68,0.89) v3(133.08,59) v3(133.08,57.99) v3(133.08,56.97) v3(133.08,55.96) v3(133.08,54.94) v3(133.08,48.84) v3(133.08,47.83) v3(133.08,46.81) v3(133.08,45.8) v3(133.08,44.78) v3(133.08,43.76) v3(133.08,42.75) v3(133.08,41.73) v3(133.08,40.72) v3(133.08,38.68) v3(133.08,37.67) v3(133.08,36.65) v3(133.08,35.64) v3(133.08,34.62) v3(133.08,33.6) v3(133.08,26.49) v3(133.08,25.48) v3(133.08,24.46) v3(133.08,23.44) v3(133.08,22.43) v3(133.08,21.41) v3(133.08,20.4) v3(133.08,19.38) v3(133.08,8.2) v3(133.08,7.19) v4(2.79,25.3) v4(2.79,24.3) v4(2.79,23.3) v4(4.29,25.3) v4(4.29,24.3) v4(4.29,23.3) v4(5.79,25.3) v4(5.79,24.3) v4(5.79,23.3) v4(12.04,25.86) v4(12.04,25.09) v4(12.8,25.86) v4(12.8,25.09) v4(98.34,23.79) v4(98.34,22.52) v4(98.34,21.25) v4(99.61,23.79) v4(99.61,21.25) v4(100.88,23.79) v4(100.88,22.52) v4(100.88,21.25)
VBAT_12V:
  vias: v2(3.05,38.1) v2(3.1,39.32) v2(7.75,51.31) v2(9.02,52.58) v2(9.02,51.31) v2(32.51,47.11) v2(32.51,45.84)
VBAT_12V_EN: length 5.2
  TOP w0.254: U74.3 3.66,28.09 2.98,28.77 2.98,29.86 2.39,30.45 R706.1 R707.2
VCC_1V2: length 10
  BOTTOM w0.381: R905.1 25.96,30.1 24.51,30.1 24,30.61 24,33.66 24.58,34.23 C670.1
  BOTTOM w0.508: U77.5 C673.1 C670.1
VCC_1V8: length 1.3
  BOTTOM w0.508: R103.2 C120.1
VCC_2V8: length 6.8
  BOTTOM w0.381: R907.1 28.51,39.05 28.19,39.37 28.19,40.89 28.77,41.47 C674.1
  BOTTOM w0.508: U78.5 C677.1 C674.1
VCC_3V3: length 10.1
  SIG1 w0.163: 62.38,36.25 v3(62.35,36.25)
  SIG2 w0.635: 18.2,35.5 v1(18.2,35.49)
  BOTTOM w0.144: 62.25,36.25 v3(62.35,36.25)
  BOTTOM w0.254: R609.2 v1(27.1,44.65)
  BOTTOM w0.381: C672.1 27.98,35.93 v1(27.51,35.46)
  BOTTOM w0.508: C672.1 FB67.2 ; v2(22.33,41.31) 22.27,41.36 22.27,41.66 21.88,42.05 FB51.2 ; FB68.2 C676.1 33.64,43.16 32.89,42.42 v1(32.89,42.01) ; FB33.1 C615.1
  vias: v1(2.79,49.66) v1(2.79,48.64) v1(10.41,35.4) v1(13.08,15.34) v1(14.22,15.34) v1(28.96,19.18) v1(32.26,13.97) v1(33.4,13.97) v1(34.67,13.97) v1(36.2,13.97) v1(60.83,44.58) v1(101.22,32.13) v1(101.73,28.32) v1(101.73,27.56) v1(111.25,51.05) v1(111.25,49.91) v2(29.01,3.81) v2(30.28,3.81) v2(51.94,24.26)
VCC_3V3_LDO2: length 9.2
  BOTTOM w0.381: R772.1 29.84,31.1 29.84,32.79 29.63,33.01 29.63,33.55 30.31,34.23 U77.1
  BOTTOM w0.508: U77.1 C732.2 C750.1 32.44,35.93 FB67.1
VCC_3V3_LDO3: length 8.6
  BOTTOM w0.381: U78.1 34,41.47 33.62,41.09 R774.1
  BOTTOM w0.508: U78.1 C731.2 36.26,41.67 C751.1 FB68.1
VCC_5V: length 34.2
  TOP w0.254: R709.2 2.17,15.53 2.33,15.37 v1(4.7,15.37)
  SIG2 w0.254: 16.69,31.5 16.76,31.42 v2(16.76,31.29)
  BOTTOM w0.254: v2(16.76,31.29) 15.82,31.29 14.61,32.51 14.61,33.02 14.07,33.56 7.65,33.56 6.33,32.24 6.33,17 v1(4.7,15.37)
  BOTTOM w0.508: FB52.2 v1(19.37,41.12)
  vias: v1(40.21,2.29) v1(46.27,35.85) v1(49.53,2.22) v1(119.51,53.34) v1(120.4,53.34) v2(17.91,31.29) v2(115.24,6.22) v2(119.76,11.05) v2(122.76,9.07)
VIN_12V:
  vias: v1(72.26,61.09) v1(72.26,60.07) v1(72.26,59.05) v1(73.28,60.07) v1(73.28,59.05) v1(74.3,60.07) v1(74.3,59.05)
CONN_GND:
  vias: v1(59.56,57.02) v1(59.56,55.88) v1(59.56,54.74) v1(60.71,57.02) v1(60.71,55.88) v1(60.71,54.74) v1(61.85,57.02) v1(61.85,55.88) v1(62.99,57.02) v1(62.99,55.88) v1(64.14,57.02) v1(64.14,55.88) v1(65.28,57.02) v1(65.28,55.88) v1(66.42,57.02) v1(66.42,55.88) v1(67.82,61.21) v1(67.82,60.2) v1(68.83,59.31) v1(68.83,58.29) v1(68.83,57.28)
LDO1_EN: length 3.6
  BOTTOM w0.254: R922.1 R921.2 R711.1 U13.5
LDO1_FB: length 3.9
  BOTTOM w0.356: U13.3 12.75,27.41 13.02,27.69 C120.2
  BOTTOM w0.508: R103.1 C120.2 R102.1
LDO2_EN: length 3.8
  BOTTOM w0.254: 32.64,30.94 R895.1 R772.2 30.58,31.98 30.93,32.33 U77.3
LDO3_EN: length 3.4
  BOTTOM w0.254: R773.1 R896.1 R774.2 U78.3
VOUT_18V: length 48.8
  SIG1 w1.016: v1(53.59,60.2) 54.36,59.44 64.51,59.44 65.53,60.45 J74.8
  SIG2 w0.762: v1(53.59,60.2) 48.01,54.61 44.58,54.61 42.59,52.62 40.33,52.62 38.9,54.05 29.29,54.05 v1(28.7,53.47)
  BOTTOM w0.254: R607.2 30.36,51.27 D87.2
  BOTTOM w0.381: R607.2 30.86,48.51 31.22,48.16 C485.1
N16733345:
  vias: v1(59.56,48.82) v1(59.56,47.68) v1(60.71,48.82) v1(60.71,47.68) v1(61.85,48.82) v1(61.85,47.68) v1(62.99,48.82) v1(62.99,47.68) v1(64.14,48.82) v1(64.14,47.68) v1(65.28,48.82) v1(65.28,47.68) v1(66.42,49.96) v1(67.56,49.96)
N16733349:
  vias: v1(51.56,48.64) v1(51.56,47.5) v1(52.7,48.64) v1(52.7,47.5) v1(53.85,48.64) v1(53.85,47.5) v1(54.99,48.64) v1(54.99,47.5) v1(56.13,48.64) v1(56.13,47.5)
N16733425: length 1.3
  TOP w0.144: C733.2 R839.1
N16733771: length 4.3
  TOP w0.144: U74.6 C592.2 C614.2
N16733783: length 1.6
  TOP w0.144: C614.1 R720.2
N16733885: length 2.2
  TOP w0.144: U74.4 C593.2
N16733923: length 6.7
  TOP w0.254: U74.1 v1(6.98,27.17) ; C594.2 v1(9.27,23.12)
  SIG1 w0.254: v1(9.27,23.12) 6.98,25.41 v1(6.98,27.17)
N16734049:
  vias: v1(69.98,50.8) v1(69.98,49.66) v1(69.98,47.04) v1(71.12,50.8) v1(71.12,49.66) v1(71.12,47.04) v1(72.26,50.8) v1(72.26,47.04) v1(73.41,50.8) v1(73.41,47.04) v1(74.55,47.04) v1(75.69,47.04) v1(76.83,47.04)
N16734163: length 4.4
  TOP w0.254: U74.5 2.39,19.15 R710.2 R709.1
N16734965: length 1.4
  TOP w0.254: D3.2 R19.1
N16737795: length 3
  BOTTOM w0.254: U77.4 27.81,32.33 R904.1 R905.2
N16737935: length 2.9
  BOTTOM w0.254: U78.4 30.88,39.57 R907.2 R908.2
N16741257: length 4.7
  BOTTOM w0.254: U25.3 28.41,48.51 R607.1 29.62,48.36 C485.2 R608.2

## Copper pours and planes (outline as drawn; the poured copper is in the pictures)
GND on TOP: 126.75,0.51 1.4,0.51 0.51,1.4 0.51,55.24 1.14,55.24 1.27,55.12 1.27,5.33 5.33,1.27 110.87,1.27 111.25,1.65 117.47,1.65 117.86,2.03 118.87,2.03 119.63,1.27 126.87,1.27 127,1.14 127,0.76 ; 1 cut-out
GND on TOP: 0.51,0.51 0.51,69.49 133.49,69.49 133.49,0.51
GND on TOP, GND: 133.35,6.73 132.97,6.73 132.72,6.99 132.72,67.44 131.32,68.83 46.1,68.83 45.59,69.34 45.59,69.49 132.69,69.49 133.49,68.69 133.49,6.87 ; 1 cut-out
GND on BOTTOM: 1.4,0.51 0.64,1.27 0.64,55.12 0.76,55.24 1.14,55.24 1.27,55.12 1.27,5.33 5.33,1.27 126.87,1.27 127,1.14 127,0.76 126.75,0.51
GND on BOTTOM: 22.73,48.01 22.73,46.1 22.86,45.97 25.15,45.97 25.4,46.23 27.56,46.23 27.69,46.35 27.69,48.64 28.19,49.15 28.96,49.15 29.21,49.4 29.21,51.31 28.83,51.69 26.04,51.69 25.78,51.44 25.78,50.04 26.67,49.15 26.67,47.37 26.42,47.12 25.53,47.12 24.51,48.13 23.11,48.13 22.99,48.26
GND on BOTTOM: 42.55,14.35 42.29,14.35 42.16,14.22 42.16,9.14 42.55,8.76 43.31,8.76 43.56,9.02 43.56,11.18 42.55,12.19
GND on BOTTOM: 0.51,0.51 0.51,69.49 133.49,69.49 133.49,0.51 ; 1 cut-out
GND on GND: 0.51,0.51 0.51,69.49 133.49,69.49 133.49,0.51 ; 5 cut-outs
GND on SIG1: 126.75,0.51 1.4,0.51 0.64,1.27 0.64,55.12 0.76,55.24 1.14,55.24 1.27,55.12 1.27,5.33 5.33,1.27 126.87,1.27 127,1.14 127,0.76 ; 1 cut-out
GND on SIG1: 133.35,6.73 132.97,6.73 132.72,6.99 132.72,67.44 131.32,68.83 46.1,68.83 45.59,69.34 45.59,69.49 132.69,69.49 133.49,68.69 133.49,6.87 ; 2 cut-outs
GND on SIG1: 1.14,55.63 0.38,56.39 0.38,68.71 1.17,69.49 51.92,69.49 52.58,68.83 52.58,57.02 51.18,55.63 ; 4 cut-outs
GND on SIG2: 133.35,6.73 132.97,6.73 132.72,6.99 132.72,67.44 131.32,68.83 39.24,68.83 38.99,69.09 38.99,69.22 39.27,69.49 132.69,69.49 133.49,68.69 133.49,6.87 ; 2 cut-outs
GND on SIG2: 0.51,58.55 0.51,69.49 53.57,69.49 53.85,69.22 53.72,69.22 49.4,64.9 49.4,55.37 44.45,55.37 42.29,53.21 39.75,53.21 38.48,54.48 0.51,54.48 ; 2 cut-outs
GND on SIG2: 1.14,55.24 1.27,55.12 1.27,5.33 5.33,1.27 126.87,1.27 127,1.14 127,0.76 126.75,0.51 1.4,0.51 0.64,1.27 0.64,5.84 0.51,5.97 0.51,55.12 0.64,55.24 ; 1 cut-out
GND on VCC: 0.51,69.49 5.97,69.49 5.99,69.47 127.64,69.47 127.76,69.34 132.08,69.34 133.48,67.94 133.48,7.11 133.22,6.86 132.97,6.86 132.72,7.11 132.72,66.42 130.3,68.83 67.44,68.83 67.18,68.58 67.18,60.58 58.55,51.94 58.55,47.5 58.8,47.24 64.77,47.24 65.41,46.61 65.41,44.2 64.52,43.31 62.99,43.31 62.36,43.94 62.36,44.83 61.72,45.47 58.17,45.47 58.04,45.34 58.04,42.29 59.31,41.02 59.31,39.5 58.04,38.23 58.04,36.07 55.37,33.4 52.07,33.4 52.07,30.61 54.86,27.81 54.86,19.05 54.74,18.92 53.98,18.92 53.85,19.05 53.85,28.32 53.34,28.83 47.62,28.83 46.48,29.97 44.45,29.97 43.81,29.34 43.81,19.18 43.56,18.92 42.55,18.92 42.16,19.3 42.16,34.29 44.83,36.96 44.83,41.4 43.94,42.29 43.94,45.85 42.29,47.5 34.8,47.5 34.54,47.75 34.54,52.83 33.78,53.59 5.33,53.59 3.94,54.99 0.76,54.99 0.51,55.24 ; 2 cut-outs
GND on VCC: 1.14,55.24 1.27,55.12 1.27,5.33 5.33,1.27 126.87,1.27 127,1.14 127,0.76 126.75,0.51 1.4,0.51 0.64,1.27 0.64,6.22 0.51,6.35 0.51,55.12 0.64,55.24 ; 1 cut-out
VBAT_12V on TOP: 47.24,47.88 47.24,49.78 46.99,50.04 45.85,50.04 45.59,49.78 45.59,49.28 44.53,48.21 31.52,48.21 31.32,48.01 31.32,42.62 31.52,42.42 41.27,42.42 42.42,43.56 46.53,43.56 46.79,43.81 46.79,44.88 47.62,45.72 47.62,47.5
VBAT_12V on TOP: 4.32,26.16 4.45,26.04 5.46,26.04 5.59,26.16 5.59,40.13 5.46,40.26 2.54,40.26 2.29,40.01 2.29,32.92 2.9,32.31 2.9,30.89 3.05,30.73 3.05,30.33 3.35,30.02 3.35,29.13 4.32,28.17
VBAT_12V on SIG1: 4.83,46.1 6.73,44.2 33.91,44.2 34.26,44.55 34.26,54.61 5.33,54.61 4.83,54.1
VBAT_12V on SIG2: 2.79,36.83 7.24,36.83 14.92,44.51 33.34,44.51 33.66,44.83 33.66,47.5 33.53,47.62 14.48,47.62 13.84,48.26 13.84,52.32 12.95,53.21 2.16,53.21 1.65,52.7 1.65,37.97
VBAT_12V on VCC: 33.78,45.85 34.04,46.1 34.04,54.1 32.51,55.63 9.14,55.63 7.56,54.04 7.56,50.16 8.89,48.83 8.89,46.99 10.03,45.85
VCC_1V8 on BOTTOM: 10.54,26.7 10.79,26.44 11.46,26.44 11.68,26.67 11.68,27.43 11.94,27.69 12.19,27.69 12.45,27.94 12.45,30.1 11.18,31.37 9.02,31.37 8.89,31.24 8.89,30.48 9.02,30.35 10.29,30.35 10.54,30.1
VCC_3V3 on BOTTOM: 10.79,17.02 10.79,16 11.18,15.62 11.18,14.73 11.3,14.61 14.48,14.61 14.86,14.99 14.86,15.88 14.73,16 12.83,16 12.57,16.26 12.57,16.89 12.32,17.14 10.92,17.14
VCC_3V3 on VCC: 0.51,7.87 0.51,56.9 35.56,56.9 45.21,47.24 45.21,36.83 48.39,33.66 56.52,33.66 58.67,35.81 58.67,44.45 59.18,44.96 60.96,44.96 62.87,43.05 64.64,43.05 65.66,44.07 65.66,46.48 66.04,46.86 68.71,46.86 69.34,46.23 77.72,46.23 78.49,46.99 78.49,58.8 73.53,63.75 68.07,63.75 67.69,64.14 67.69,68.33 67.82,68.45 128.78,68.45 132.21,65.02 132.21,3.56 130.43,1.78 6.86,1.78 0.76,7.87 ; 2 cut-outs
VCC_3V3_LDO on BOTTOM: 11.81,23.24 11.68,23.37 11.68,24.38 11.56,24.51 11.05,24.51 10.92,24.38 10.92,19.3 10.67,19.05 10.67,17.78 10.79,17.65 12.32,17.65 12.83,18.16 12.83,22.86 12.45,23.24
VCC_5V on TOP: 18.67,31.5 18.41,31.75 16.38,31.75 16.13,31.5 16.13,29.46 15.75,29.08 15.75,17.27 16.26,16.76 21.84,16.76 21.97,16.89 21.97,22.76 21.46,23.27 21.46,30.1 21.34,30.23 20.45,30.23 20.19,29.97 19.05,29.97 18.67,30.35
VCC_5V on SIG2: 21.78,28.13 18.92,30.99 18.92,33.27 17.27,34.92 17.27,36.32 17.65,36.7 27.56,36.7 28.83,35.43 36.58,35.43 37.85,34.16 45.72,34.16 47.24,35.69 47.24,39.37 45.72,40.89 22.1,40.89 21.34,41.66 18.41,41.66 10.41,33.66 10.41,30.1 11.18,29.34 11.18,1.78 11.56,1.4 122.68,1.4 123.89,2.6 123.89,5.4 123.95,5.46 123.95,17.02 127.38,20.45 127.38,57.02 124.21,60.2 119.76,60.2 119.13,59.56 119.13,26.42 114.55,21.84 107.19,21.84 101.73,16.38 93.73,16.38 93.6,16.51 88.9,16.51 85.22,12.83 35.56,12.83 34.48,11.75 22.67,11.75 21.78,12.64
VCC_FIL on BOTTOM: 18.8,45.97 22.1,45.97 22.48,45.59 25.4,45.59 25.65,45.85 26.42,45.85 26.54,45.72 26.54,44.58 26.29,44.32 21.84,44.32 21.72,44.2 21.72,43.18 21.59,43.05 18.8,43.05 18.67,43.18 18.67,45.85
VIN_12V on TOP: 74.8,60.45 73.79,60.45 73.53,60.71 73.53,61.59 71.88,63.25 70.1,63.25 69.85,62.99 69.85,55.88 70.1,55.63 75.44,55.63 75.69,55.88 75.69,59.56
VIN_12V on BOTTOM: 73.79,60.45 73.53,60.71 73.53,61.59 71.88,63.25 70.1,63.25 69.85,62.99 69.85,57.02 68.58,55.75 68.58,51.94 68.71,51.82 72.39,51.82 73.15,52.58 77.6,52.58 77.72,52.7 77.72,57.53 74.8,60.45
VIN_12V on GND, SIG1: 75.44,55.63 75.69,55.88 75.69,59.56 74.8,60.45 73.79,60.45 73.53,60.71 73.53,61.59 71.88,63.25 70.1,63.25 69.85,62.99 69.85,55.88 70.1,55.63
VIN_12V on SIG2, VCC: 75.44,55.63 75.69,55.88 75.69,59.56 74.8,60.45 73.79,60.45 73.53,60.71 73.53,61.59 71.88,63.25 70.1,63.25 69.85,62.99 69.85,55.88 70.1,55.63
CONN_GND on TOP: 67.44,60.2 64.77,57.53 59.31,57.53 59.05,57.28 59.05,51.82 59.18,51.69 68.71,51.69 68.96,51.94 68.96,55.24 69.34,55.63 69.34,62.99 69.22,63.12 67.56,63.12 67.44,62.99
CONN_GND on BOTTOM: 68.07,56.01 69.34,57.28 69.34,62.99 69.22,63.12 67.56,63.12 67.44,62.99 67.44,60.2 64.77,57.53 59.31,57.53 59.05,57.28 59.05,51.82 59.18,51.69 67.94,51.69 68.07,51.82
CONN_GND on GND: 69.34,62.99 69.34,55.63 68.96,55.24 68.96,51.94 68.71,51.69 59.18,51.69 59.05,51.82 59.05,57.28 59.31,57.53 64.77,57.53 67.44,60.2 67.44,62.99 67.56,63.12 69.22,63.12
CONN_GND on SIG1: 69.34,62.99 69.34,55.63 68.96,55.24 68.96,51.94 68.71,51.69 59.18,51.69 59.05,51.82 59.05,57.28 59.31,57.53 64.77,57.53 67.44,60.2 67.44,62.99 67.56,63.12 69.22,63.12
CONN_GND on SIG2: 69.34,62.99 69.34,57.28 68.07,56.01 68.07,51.82 67.94,51.69 59.18,51.69 59.05,51.82 59.05,57.28 59.31,57.53 64.77,57.53 67.44,60.2 67.44,62.99 67.56,63.12 69.22,63.12
CONN_GND on VCC: 69.34,62.99 69.34,57.28 68.07,56.01 68.07,51.82 67.94,51.69 59.18,51.69 59.05,51.82 59.05,57.28 59.31,57.53 64.77,57.53 67.44,60.2 67.44,62.99 67.56,63.12 69.22,63.12
VOUT_18V on BOTTOM: 23.37,54.23 23.37,52.07 23.5,51.94 29.21,51.94 29.46,51.69 29.46,50.93 29.72,50.67 32,50.67 32.13,50.8 32.13,54.36 32,54.48 23.62,54.48
N16733345 on TOP: 68.45,47.37 68.76,47.37 68.83,47.45 68.83,50.93 68.58,51.18 59.18,51.18 59.05,51.05 59.05,47.5 59.18,47.37 60.58,47.37
N16733345 on BOTTOM: 59.18,47.37 68.71,47.37 68.83,47.5 68.83,50.93 68.58,51.18 59.18,51.18 59.05,51.05 59.05,47.5
N16733345 on GND, SIG1, SIG2, VCC: 68.83,50.93 68.58,51.18 59.18,51.18 59.05,51.05 59.05,47.5 59.18,47.37 68.71,47.37 68.83,47.5
N16733349 on TOP: 53.21,51.05 52.96,50.8 52.96,49.91 52.7,49.66 51.05,49.66 50.67,50.04 49.66,50.04 49.53,49.91 49.53,47.88 49.28,47.62 49.28,45.72 49.4,45.59 50.19,45.59 50.7,46.1 58.09,46.1 58.27,46.28 58.27,50.93 58.14,51.05
N16733349 on BOTTOM: 56.64,47.24 56.64,49.78 56.52,49.91 51.31,49.91 51.18,49.78 51.18,47.24 51.31,47.12 56.52,47.12
N16733417 on TOP: 5.84,22.48 5.84,20.19 6.35,19.68 6.35,19.18 6.48,19.05 7.11,19.05 7.37,18.8 7.37,10.54 7.62,10.29 11.43,10.29 12.06,10.92 12.06,22.23 11.68,22.61 5.97,22.61
N16734049 on TOP, GND, SIG1: 69.85,55.12 69.47,54.74 69.47,46.86 69.6,46.74 77.47,46.74 77.72,46.99 77.72,54.74 77.34,55.12
N16734049 on BOTTOM: 73.41,52.07 72.64,51.31 69.6,51.31 69.47,51.18 69.47,46.86 69.6,46.74 77.47,46.74 77.72,46.99 77.72,51.94 77.6,52.07
N16734049 on SIG2, VCC: 69.47,51.18 69.47,46.86 69.6,46.74 77.47,46.74 77.72,46.99 77.72,51.94 77.6,52.07 73.41,52.07 72.64,51.31 69.6,51.31
N16741203 on BOTTOM: 24.38,48.64 25.53,47.5 26.29,47.5 26.42,47.62 26.42,48.9 25.15,50.16 20.83,50.16 18.54,47.88 18.54,46.86 18.67,46.74 22.1,46.74 22.23,46.86 22.23,48.51 22.35,48.64

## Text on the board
BOTTOM: L6-BOTTOM
Ref Des/Assembly Bottom: ASSEMBLY BOTTOM
Package Geometry/Pastemask Bottom: PASTEMASK BOTTOM
Ref Des/Silkscreen Bottom: SILKSCREEN BOTTOM
User.Comments: THIS DOCUMENT CONTAINS INFORMATION | PROPRIETARY TO iWAVE SYSTEMS AND SHALL | NOT BE USED FOR ENGINEERING DESIGN | PROCUREMENT OR MANUFACTURE IN WHOLE | OR IN PART WITHOUT THE CONSENT OF | iWAVE SYSTEMS. | DRAWN | CHECKED | APPROVED | APPROVALS | DATE | TOLERANCES ARE: | ALL DIMENSIONS ARE IN: | MILLIMETERS | DECIMALS | INCHES | ____ | ANGLES | 1.0 | x.x | DRAWING TITLE | SCALE | SIZE | 1/1 | DO NOT SCALE DRAWING | iWave Systems technolgies Pvt. Ltd. | 7/B 29th Main BTM Layout, 2nd Stage, | Bangalore-560076, India | Web:www.iwavesystems.com | SHEET | 1  OF | DD-MM-YYYY | 1 | UNLESS OTHERWISE SPECIFIED | REV | ORIGINAL RELEASE | DESCRIPTION | REVISIONS | PRINTED CIRCUIT BOARD | D | SOLDERMASK BOTTOM | SOLDERMASK TOP
TOP: L1-TOP
Ref Des/Assembly Top: ASSEMBLY TOP
Package Geometry/Pastemask Top: PASTEMASK TOP
Ref Des/Silkscreen Top: SILKSCREEN TOP
SIG1: L3-SIG1
SIG2: L4-SIG2
PAGE_OUTLINE: FAB DETAILS | D | C | B | A | 8 | 7 | 6 | 5 | 4 | 3 | 2 | 1
User.8: L2-GND
User.9: L4-VCC
User.10: L9-VCC2
User.11: L7-GND2
User.14: L6-SIG6
User.15: L8-SIG4
User.16: FILM:
User.18: XXXXX | DD-MM-YYYY | P/N: | iW-XXXXX-BF-XX-RX.X-RELX.XX | XXXXXXXXXXXXXX | X
User.19: PREPREG | LAYER STACK UP | LAYER1-TOP | LAYER2-XXX | LAYER3-XXX | LAYER4-XXX | LAYER5-XXX | LAYER6-XXX | LAYER7-XXX | LAYER8-XXX | LAYER9-XXX | TOP SILKSCREEN | TOP SOLDERMASK | LAYER10-BOTTOM | BOTTOM SOLDERMASK | BOTTOM SILKSCREEN
User.21: CORE
User.25: 15.Fab Vendor is not to alter the supplied film or database without getting permission from iWave Systems technologies. | 16.Board impedance details are as shown below. For more information refer XXlayer_XXX.pdf provided with the gerber data | 10.Suppress unused pads for plated-through holes on internal conductor layers. | 11.Add Tear drop to all signal layers | 14.Electrical Test: All boards should be 100% electrically  tested for opens & shorts | 13.Finish boards shall not have nicks, scratches, voids, exposed copper,poor plating and mis-drilled holes | 12.The PWB will be marked as lead free process compatible by use of an Ink stamp | 17.Impedance control is required  for the board | 3.Solder mask (SMOBC)- Apply LPI Solder mask on both sides per IPC-SM-840,type B,class 3,color green | 4.Silkscreen- White Epoxy ink,both sides .No silk on pads | 5.Board thickness shall be _______ mm and tolerance +/- _____ | 6.Minimum Trace width and clearances are ___/___mils | 7.DRC's must be run on the Gerber before building boards | 1.PCB  fabrication shall meet the requirements of  IPC-A-600, class 2 (latest version ) | 2.Surface finish shall be - ENIG | 8.RS274X GERBER/ODB++ used for the fab must be verified against the IPC356A netlist | 9.This Fabrication process should be RoHS Complaint | LAYERS | IMPEDANCE | (Ohms) | SINGLE ENDED | TRACE | (MILS) | WIDTH | DIFFERENTIAL | SPACING
